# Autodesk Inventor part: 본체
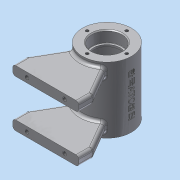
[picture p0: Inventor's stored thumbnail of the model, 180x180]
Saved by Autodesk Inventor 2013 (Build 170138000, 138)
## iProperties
Created: 2018-05
Part Number: 본체
Material: 알루미늄 6061
Document SubType Name: Modeling
Designer: dgall
Density: 2.71 g/cm^3
Mass: 318.546 g
Surface Area: 375.93 cm^2
Volume: 117.545 cm^3
Author: dgall
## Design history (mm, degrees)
sketch "스케치1"
  geometry: C1 r 26 at (0, 0); 1 further point
  constraints: 1 centre point, 1 coincident
  dimensions: "d0" = 52 diameter of C1
extrude "돌출1" new body sketch "스케치1" stored distance "d1" = 70; taper "d2" = 0 deg
node "작업 평면1"
sketch "스케치2"
  geometry: L1 (26, -35)-(-26, -35) reference; L2 (-26, -35)-(-26, 35) reference; L3 (-26, 35)-(26, 35) reference; L4 (26, 35)-(26, -35) reference; L5 (0, 35)-(0, -35); L6 (0, 35)-(16, 35); L7 (16, 35)-(16, 23); L8 (16, 23)-(14, 23); L9 (14, 23)-(14, 21); L10 (14, 21)-(21, 21); L11 (21, 21)-(21, -21); L12 (21, -21)-(14, -21); L13 (14, -21)-(14, -23); L14 (14, -23)-(16, -23); L15 (16, -23)-(16, -35); L16 (16, -35)-(0, -35); 3 further points
  constraints: 24 end point, 7 perpendicular, 4 midpoint, 2 parallel, 2 point on line, 1 collinear, 1 horizontal alignment
  dimensions: "d4" = 32 diameter of L7 L5; "d6" = 28 diameter of L9 L5; "d7" = 12 distance of L6.end L7.end; "d8" = 32 diameter of L15 L5; "d9" = 12 distance of L14.end L15.end; "d10" = 42 distance of L10.end L11.end; "d11" = 28 diameter of L13 L5; "d12" = 42 diameter of L11 L5
revolve "회전1" sketch "스케치2" stored, may be unused: angle "d13" = 90 deg
node "작업 평면2"
sketch "스케치3"
  geometry: L1 (-35, -65)-(35, -65); L2 (-35, -65)-(-35, -50); L3 (35, -65)-(35, -50); L4 (-35, -50)-(-17.325, -19.386); L5 (35, -50)-(17.325, -19.386); C1 r 16 at (0, 0) reference; A1 r 26 centre (0, 0) between (-17.325, -19.386) and (17.325, -19.386) reference; 2 further points
  constraints: 10 end point, 2 point on circle, 1 horizontal, 1 midpoint, 1 parallel, 1 perpendicular, 1 vertical alignment
  dimensions: "d15" = 70 distance of L1.start L1.end; "d16" = 65 distance from line of L1 point (0, 0); "d17" = 15 distance of L1.start L2.end; "d18" = 15 distance of L1.end L3.end; "d19" = 30 deg angle of L4 L2; "d20" = 30 deg angle of L5 L3
extrude "돌출2" join sketch "스케치3" distance "d21" = 10; taper "d22" = 0 deg
node "작업 평면3"
node "작업 평면4"
sketch "스케치4"
  geometry: C1 r 5 at (0, 0); 1 further point
  constraints: 1 centre point, 1 coincident
  dimensions: "d25" = 10 diameter of C1
extrude "돌출3" join sketch "스케치4" stored distance "d26" = 10; taper "d27" = 0 deg
sketch "스케치5"
  geometry: L1 (-5, 25.515)-(-5, 29) reference; L2 (-5, 29)-(5, 29) reference; L3 (5, 29)-(5, 25.515) reference; L4 (0, 0)-(-9.919, -27.251); L5 (0, 0)-(0, -9.235); C1 r 21 at (0, 0) reference; A1 r 26 centre (0, 0) between (-5, 25.515) and (5, 25.515) reference; 1 further point
  constraints: 4 end point, 1 parallel
  dimensions: "d28" = 29 distance of L4.start L4.end; "d29" = 20 deg angle of L5 L4
  node "절단 모서리 투영3"
node "작업 평면5"
sketch "스케치6"
  geometry: C1 r 6 at (0, 0); 1 further point
  constraints: 1 centre point, 1 coincident
  dimensions: "d30" = 12 diameter of C1
extrude "돌출4" join sketch "스케치6" stored distance "d31" = 10; taper "d32" = 0 deg
sketch "스케치7"
  geometry: C1 r 16 at (0, 0) reference; C2 r 26 at (0, 0) reference; A1 r 21 centre (0, 0) between (0, 21) and (-21, 0); 2 further points
  constraints: 4 point on circle, 2 horizontal alignment, 2 vertical alignment, 1 centre point, 1 coincident
  dimensions: "d33" = 42 diameter of A1
hole "구멍1" sketch "스케치7" at (0, 21), (-21, 0), (0, -21), (21, 0) diameter "d34" = 3.242; stored, may be unused: countersink angle "d38" = 90 deg, drill point angle "d40" = 118 deg; dims "d35" = 8, "d36" = 4, "d37" = 2, "d39" = 10
sketch "스케치8"
  geometry: C1 r 5 at (0, 0) reference; C2 r 3 at (0, 0)
  constraints: 1 centre point, 1 coincident
  dimensions: "d41" = 6 diameter of C2
extrude "돌출5" cut sketch "스케치8" distance "d42" = 20; taper "d43" = 0 deg
feature "스레드1" dims "d44" = 10, "d45" = 0
sketch "스케치9"
  geometry: C1 r 6 at (0, 0) reference; C2 r 3 at (0, 0)
  constraints: 1 centre point, 1 coincident
  dimensions: "d46" = 6 diameter of C2
extrude "돌출6" cut sketch "스케치9" distance "d47" = 20; taper "d48" = 0 deg
feature "스레드2" dims "d49" = 10, "d50" = 0
sketch "스케치10"
  geometry: L1 (0, -60)-(70, -60) reference; L2 (0, -60)-(70, -60) reference; L3 (70, -60)-(70, -50) reference; L4 (70, -50)-(0, -50) reference; L5 (0, -60)-(0, -50) reference; 6 further points
  constraints: 2 vertical alignment, 1 horizontal alignment
  dimensions: "d51" = 5 vertical distance of point (70, 0) point (55, -5); "d52" = 20 horizontal distance of point (35, -30) point (55, -5); "d53" = 40 distance of point (15, -5) point (55, -5); "d54" = 40 distance of point (15, -55) point (55, -55); "d55" = 5 vertical distance of point (55, -55) L1.end
hole "구멍2" sketch "스케치10" at (55, -5), (15, -5), (55, -55), (15, -55) diameter "d56" = 4.134; stored, may be unused: countersink angle "d60" = 90 deg, drill point angle "d62" = 118 deg; dims "d57" = 8, "d58" = 4, "d59" = 2, "d61" = 10
fillet "모깎기1" dims "d63" = 0.3
fillet "모깎기2" dims "d64" = 3
fillet "모깎기3" dims "d65" = 2
fillet "모깎기4" dims "d66" = 3
fillet "모깎기5" dims "d67" = 3
fillet "모깎기6" dims "d68" = 3
chamfer "모따기1" distance "d69" = 1; stored, may be unused: second distance "d70" = 2, angle "d71" = 45 deg
node "작업 평면6"
sketch "스케치11"
  geometry: L1 (26, 35)-(-26, 35) reference; L2 (26, -35)-(26, 35) reference; 2 further points
  constraints: 1 coincident, 1 other
feature "엠보싱1" sketch "스케치11" dims "d72" = 0.5, "d73" = 0
node "솔리드1"
mirror "대칭1"
mirror "대칭2"
node "투영된 루프1"
node "절단 모서리 투영1"
node "절단 모서리 투영2"
other parameters: "d3" = 0, "d23" = 0, "d24" = 29
